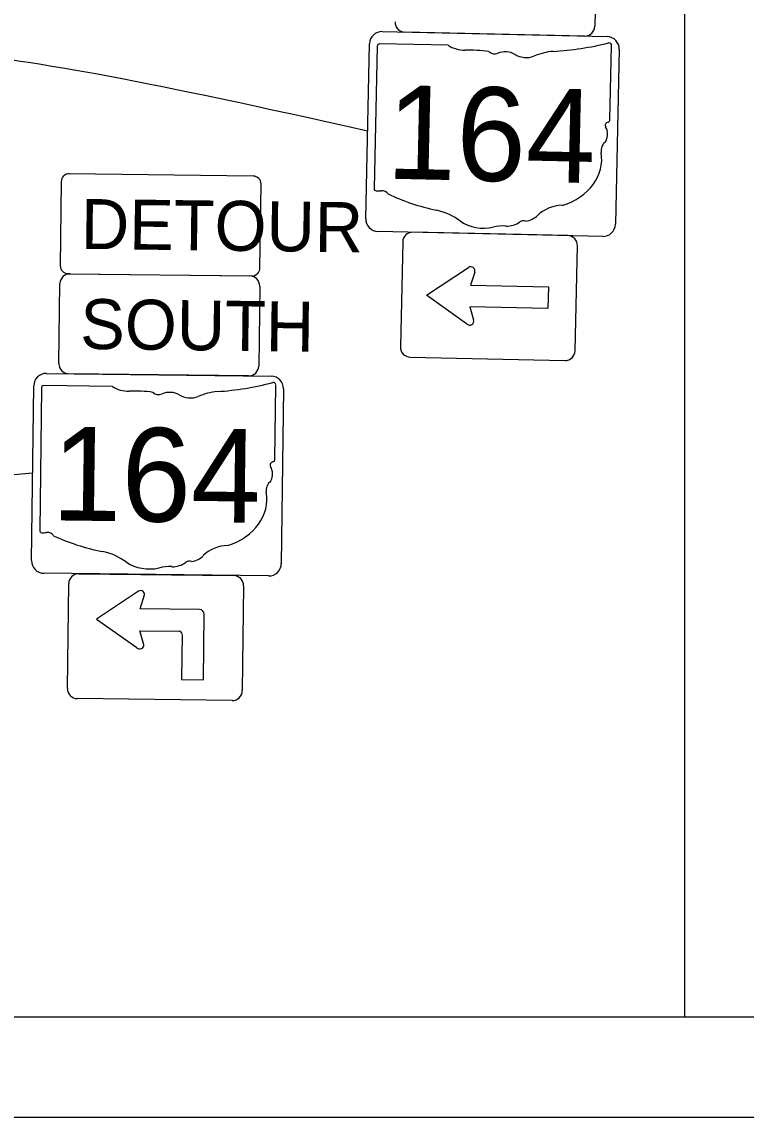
# Model space of a CAD drawing. Extents: x -202 to 1556, y 0 to 676.
# Drawn here: x 283.6 to 356.1, y 0 to 109.6 of the extents above; entities that cross this region are included whole.
import ezdxf

# ---------------------------------------------------------------- set-up
doc = ezdxf.new("R2010")
doc.units = 0
for name, color, linetype in [('GM_X_Minor_Lake', 7, 'Continuous'), ('GM_X_Minor_Lake_Text', 7, 'Continuous'), ('GM_X_Minor_River_Text', 7, 'Continuous'), ('SH_Border', 7, 'Continuous'), ('SH_Cut_Line', 7, 'Continuous'), ('SH_Data', 7, 'Continuous')]:
    doc.layers.add(name, color=color, linetype=linetype)

msp = doc.modelspace()

# ---------------------------------------------------------------- linework, layer by layer
at = {"layer": 'GM_X_Minor_Lake'}
for p, q in [((341.16, 117.14), (340.99, 109.14)), ((339.96, 108.16), (321.97, 108.56)), ((319.22, 107.15), (318.91, 92.92)), ((326.32, 107.24), (319.45, 107.39)), ((342.5, 99.79), (342.66, 107.23)), ((342.5, 99.79), (342.5, 99.79)), ((288.47, 84.38), (306.46, 84.16)), ((287.35, 75.4), (287.45, 83.4)), ((307.45, 83.15), (307.35, 75.15)), ((306.34, 74.16), (288.34, 74.38)), ((285.6, 72.95), (285.43, 58.72)), ((292.7, 73.1), (285.84, 73.19)), ((308.96, 65.81), (309.05, 73.25)), ((308.95, 65.81), (308.96, 65.81)), ((289.35, 54.37), (304.84, 54.18)), ((288.2, 42.88), (288.33, 53.38)), ((305.83, 53.17), (305.7, 42.67)), ((295.22, 52.56), (291.1, 49.82)), ((295.49, 50.86), (295.92, 52.26)), ((301.43, 50.78), (295.49, 50.86)), ((301.43, 50.78), (301.43, 50.78)), ((291.1, 49.82), (295.15, 46.97)), ((301.81, 43.75), (301.89, 50.31)), ((295.86, 47.26), (295.46, 48.67)), ((295.46, 48.67), (299.37, 48.62)), ((299.68, 48.3), (299.62, 43.77)), ((299.62, 43.77), (301.81, 43.75)), ((304.69, 41.68), (289.19, 41.87))]:
    msp.add_line(p, q, dxfattribs=at)
for points in [[(319.72, 108.61), (342.21, 108.11)], [(318.06, 89.89), (318.44, 107.39)], [(343.44, 106.84), (343.05, 89.34)], [(306.79, 94.16), (288.39, 94.38)], [(287.58, 93.59), (287.48, 85.2)], [(307.47, 84.95), (307.58, 93.35)], [(341.78, 88.12), (319.28, 88.61)], [(288.27, 84.39), (306.66, 84.16)], [(286.09, 74.41), (308.59, 74.13)], [(284.61, 55.68), (284.83, 73.18)], [(309.83, 72.87), (309.61, 55.37)], [(308.34, 54.14), (285.85, 54.41)]]:
    msp.add_lwpolyline(points, dxfattribs=at)
for centre, radius, start, end in [((319.69, 107.36), 1.25, 88.742, 178.742), ((321.99, 109.56), 1, 178.742, 268.742), ((339.99, 109.16), 1, 268.742, 358.742), ((342.19, 106.86), 1.25, 358.742, 88.742), ((288.38, 93.59), 0.8, 89.2934, 179.2934), ((306.78, 93.36), 0.8, 359.2934, 89.2934), ((319.31, 89.86), 1.25, 178.742, 268.742), ((341.8, 89.37), 1.25, 268.742, 358.742), ((288.45, 83.38), 1, 89.2934, 179.2934), ((288.28, 85.19), 0.8, 179.2934, 269.2934), ((306.67, 84.96), 0.8, 269.2934, 359.2934), ((306.45, 83.16), 1, 359.2934, 89.2934), ((288.35, 75.38), 1, 179.2934, 269.2934), ((306.35, 75.16), 1, 269.2934, 359.2934), ((286.08, 73.16), 1.25, 89.2934, 179.2934), ((308.58, 72.88), 1.25, 359.2934, 89.2934), ((285.86, 55.66), 1.25, 179.2934, 269.2934), ((308.36, 55.39), 1.25, 269.2934, 359.2934), ((289.33, 53.37), 1, 89.2934, 179.2934), ((304.83, 53.18), 1, 359.2934, 89.2934), ((295.51, 52.26), 0.417, 359.295, 134.2933), ((301.42, 50.31), 0.469, 359.2934, 89.2934), ((299.37, 48.31), 0.312, 359.2934, 89.2934), ((295.45, 47.26), 0.417, 224.2935, 359.295), ((289.2, 42.87), 1, 179.2934, 269.2934), ((304.7, 42.68), 1, 269.2934, 359.2934)]:
    msp.add_arc(centre, radius, start, end, dxfattribs=at)
for centre, major_axis, start_param, end_param in [((334.73, 126.46), (24.85, -0.55), 4.814394, 5.042369), ((342.4, 107.27), (0.261, -0.006), 6.141152, 7.989035), ((319.49, 107.17), (0.271, -0.006), 1.712693, 3.28349), ((327.99, 108.85), (2.63, -0.06), 4.042523, 4.731795), ((328.65, 99.19), (9.45, -0.21), 1.404758, 1.657858), ((330.97, 106.99), (0.76, -0.017), 3.836095, 5.185415), ((332.04, 105.32), (1.58, -0.03), 0.950623, 2.079405), ((334.13, 107.54), (1.9, -0.04), 4.081561, 5.145723), ((337.38, 102.65), (5, -0.11), 1.699011, 2.107814), ((342.22, 99.76), (0.279, -0.006), 5.05454, 6.418171), ((342.43, 99.24), (0.404, -0.009), 1.883978, 3.671073), ((339.84, 98.36), (2.42, -0.05), 5.934695, 6.695948), ((343.37, 96.65), (1.76, -0.04), 2.387724, 3.262537), ((335.46, 95.88), (6.22, -0.14), 5.101752, 6.440018), ((319.18, 92.88), (0.274, -0.006), 3.00124, 4.508301), ((319.25, 94.34), (2.09, -0.05), 4.665946, 4.897461), ((319.63, 92.08), (0.754, -0.017), 0.519207, 1.627899), ((329.42, 104.66), (17.94, -0.39), 4.195997, 4.488961), ((337.92, 88.51), (3.4, -0.07), 1.647645, 2.488434), ((323.67, 86.42), (5.61, -0.12), 0.823519, 1.323587), ((333.66, 91.22), (2.01, -0.04), 4.937069, 5.64225), ((329.86, 91.79), (3.56, -0.08), 4.026481, 4.996735), ((331.81, 86.82), (2.93, -0.06), 1.495662, 1.94098), ((332.16, 90.67), (1.9, -0.04), 4.691044, 5.507374), ((333.84, 89.26), (0.534, -0.012), 1.147584, 2.315152), ((300.93, 92.4), (24.85, -0.31), 4.814394, 5.042369), ((308.79, 73.29), (0.261, -0.003), 6.141152, 7.989035), ((285.87, 72.97), (0.271, -0.003), 1.712693, 3.28349), ((294.36, 74.73), (2.63, -0.03), 4.042523, 4.731795), ((295.11, 65.08), (9.45, -0.12), 1.404758, 1.657858), ((297.35, 72.9), (0.76, -0.009), 3.836095, 5.185415), ((298.45, 71.25), (1.58, -0.02), 0.950623, 2.079405), ((303.81, 68.62), (5, -0.06), 1.699011, 2.107814), ((300.52, 73.48), (1.9, -0.02), 4.081561, 5.145723), ((308.68, 65.79), (0.279, -0.003), 5.05454, 6.418171), ((308.89, 65.26), (0.404, -0.005), 1.883978, 3.671073), ((306.31, 64.36), (2.42, -0.03), 5.934695, 6.695948), ((309.85, 62.68), (1.76, -0.02), 2.387724, 3.262537), ((301.95, 61.83), (6.22, -0.08), 5.101752, 6.440018), ((285.7, 58.68), (0.274, -0.003), 3.00124, 4.508301), ((285.76, 60.14), (2.09, -0.03), 4.665946, 4.897461), ((286.16, 57.89), (0.754, -0.009), 0.519207, 1.627899), ((295.83, 70.55), (17.95, -0.22), 4.195997, 4.488961), ((304.48, 54.49), (3.4, -0.04), 1.647645, 2.488434), ((290.26, 52.26), (5.62, -0.07), 0.823519, 1.323587), ((300.2, 57.15), (2.01, -0.02), 4.937069, 5.64225), ((296.4, 57.69), (3.56, -0.04), 4.026481, 4.996735), ((298.39, 52.74), (2.93, -0.04), 1.495662, 1.94098), ((298.7, 56.59), (1.9, -0.02), 4.691044, 5.507374), ((300.4, 55.2), (0.535, -0.007), 1.147584, 2.315152)]:
    msp.add_ellipse(centre, major_axis=major_axis, ratio=0.8, start_param=start_param, end_param=end_param, dxfattribs=at)
at = {"layer": 'GM_X_Minor_Lake_Text'}
for p, q in [((338.28, 88.2), (322.78, 88.54)), ((321.76, 87.56), (321.53, 77.06)), ((339.02, 76.68), (339.25, 87.17)), ((324.14, 82.25), (328.34, 85.01)), ((328.97, 84.53), (328.54, 83.25)), ((328.16, 79.37), (324.14, 82.25)), ((328.54, 83.25), (336.35, 83.08)), ((336.35, 83.08), (336.3, 80.89)), ((336.3, 80.89), (328.49, 81.06)), ((328.49, 81.06), (328.86, 79.77)), ((322.51, 76.04), (338, 75.7))]:
    msp.add_line(p, q, dxfattribs=at)
for centre, radius, start, end in [((322.76, 87.54), 1, 88.742, 178.742), ((338.25, 87.2), 1, 358.742, 88.742), ((328.57, 84.66), 0.417, 341.5374, 123.3308), ((328.46, 79.66), 0.417, 223.7324, 15.9466), ((322.53, 77.04), 1, 178.742, 268.742), ((338.02, 76.7), 1, 268.742, 358.742)]:
    msp.add_arc(centre, radius, start, end, dxfattribs=at)
at = {"layer": 'GM_X_Minor_River_Text'}
msp.add_line((350, 10), (350, 430), dxfattribs=at)
at = {"layer": 'SH_Border'}
msp.add_lwpolyline([(30, 430), (670, 430), (670, 10), (30, 10)], close=True, dxfattribs=at)
at = {"layer": 'SH_Cut_Line'}
msp.add_lwpolyline([(0, 0), (680, 0), (680, 440), (0, 440)], close=True, dxfattribs=at)
at = {"layer": 'SH_Data'}
for points in [[(318.25, 98.64), (296.15, 103.63), (275.17, 107.57), (247.73, 107.51), (203.85, 110.62), (195.4, 115.77)], [(284.72, 64.43), (256.93, 61.67), (237.17, 76.82), (226.21, 84.28), (208.97, 103.33), (195.2, 105.52)]]:
    msp.add_open_spline(points, degree=3, dxfattribs=at)

# ---------------------------------------------------------------- texts
at = {"layer": 'GM_X_Minor_Lake'}
for s, height, rotation, p in [('164', 9.375, 358.742, (320.07, 93.9)), ('DETOUR', 5, 359.2934, (289.53, 86.87)), ('SOUTH', 5, 359.2934, (289.46, 76.87)), ('164', 9.375, 359.2934, (286.59, 59.71))]:
    msp.add_text(s, height=height, rotation=rotation, dxfattribs=at).set_placement(p)

doc.saveas('drawing.dxf')
